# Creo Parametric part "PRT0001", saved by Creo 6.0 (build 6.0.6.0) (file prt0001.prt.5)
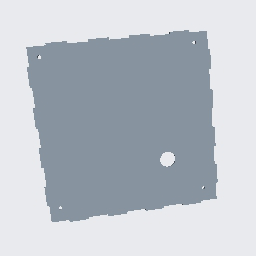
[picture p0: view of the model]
Units: Inch lbm Second (Pro/E Default); INCH, POUND, SECS

Created from: INLBS_PART_SOLID.PRT

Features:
  1. datum plane "RIGHT"
  2. datum plane "TOP"
  3. datum plane "FRONT"
  4. coordinate system
  5. sketch "Sketch 1"
  6. extrusion "Extrude 1"
  7. sketch "Sketch 2"
  8. extruded cut "Extrude 2"
  9. sketch "Sketch 3"
  10. extruded cut "Extrude 3"
  11. sketch "Sketch 4"
  12. extruded cut "Extrude 4"

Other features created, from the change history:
  extrusion "Extrude 2" (2 times)
  mirror "Mirror 1"

Surfaces: 70 plane, 5 cylinder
